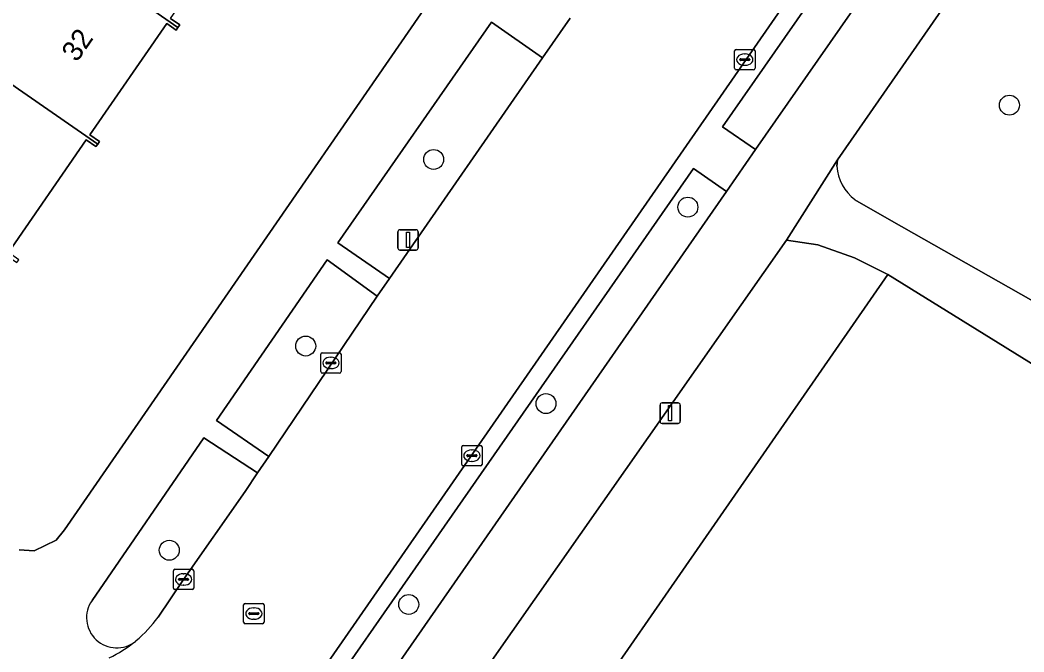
# Model space of a CAD drawing. Extents: x 160157 to 160921, y 381516 to 382045.
# Drawn here: x 160661.83 to 160711.12, y 381635.3 to 381666.31 of the extents above; entities that cross this region are included whole.
import ezdxf

# ---------------------------------------------------------------- set-up
doc = ezdxf.new("R2010")
doc.units = 0
for name, color, linetype in [('IMGEO_Berm_groen', 7, 'Continuous'), ('IMGEO_Boom', 7, 'Continuous'), ('IMGEO_Erf', 7, 'Continuous'), ('IMGEO_Fietspad_open', 7, 'Continuous'), ('IMGEO_Groenvoorziening', 7, 'Continuous'), ('IMGEO_Kolk', 7, 'Continuous'), ('IMGEO_Lichtmast', 7, 'Continuous'), ('IMGEO_Loofbos', 7, 'Continuous'), ('IMGEO_Pand', 7, 'Continuous'), ('IMGEO_Pand_nummerreeks', 7, 'Continuous'), ('IMGEO_Rijbaan_lokaal_open', 7, 'Continuous'), ('IMGEO_Rioolput', 7, 'Continuous'), ('IMGEO_Voetpad_gesloten', 7, 'Continuous'), ('IMGEO_Voetpad_open', 7, 'Continuous')]:
    doc.layers.add(name, color=color, linetype=linetype)

msp = doc.modelspace()

# ---------------------------------------------------------------- linework, layer by layer
at = {"layer": 'IMGEO_Berm_groen'}
for points in [[(160704.668, 381669.608), (160703.044, 381670.718), (160696.326, 381661.075), (160697.946, 381659.948)], [(160687.489, 381664.451), (160684.982, 381666.207), (160677.443, 381655.379), (160679.971, 381653.62)], [(160696.519, 381657.896), (160694.898, 381659.024), (160673.518, 381628.335), (160674.352, 381626.036)], [(160679.374, 381652.759), (160676.912, 381654.54), (160671.475, 381646.649), (160674.044, 381644.891)]]:
    msp.add_lwpolyline(points, close=True, dxfattribs=at)
for points in [[(160672.883, 381643.176), (160673.497, 381644.083), (160670.854, 381645.81), (160665.368, 381637.83)], [(160668.609, 381637.008), (160669.862, 381638.857), (160672.883, 381643.176)], [(160667.511, 381635.831), (160667.525, 381635.842), (160667.539, 381635.854)]]:
    msp.add_lwpolyline(points, dxfattribs=at)
for centre, radius, start, end in [((160666.58, 381636.981), 1.48, 145.0056, 308.9767), ((160663.575, 381640.603), 6.186, 309.8552, 324.4709)]:
    msp.add_arc(centre, radius, start, end, dxfattribs=at)
at = {"layer": 'IMGEO_Boom'}
for centre in [(160710.41, 381662.131), (160682.141, 381659.468), (160694.623, 381657.127), (160675.859, 381650.311), (160687.656, 381647.487), (160669.159, 381640.29), (160680.917, 381637.631)]:
    msp.add_circle(centre, 0.489, dxfattribs=at)
at = {"layer": 'IMGEO_Erf'}
for points in [[(160661.788, 381640.317), (160662.531, 381640.256), (160663.603, 381640.788), (160664.019, 381641.292), (160689.395, 381678.051)], [(160669.217, 381666.391), (160669.674, 381666.076), (160669.585, 381665.947), (160669.496, 381665.819), (160669.033, 381666.139), (160665.261, 381660.677), (160665.734, 381660.35), (160665.647, 381660.223), (160665.559, 381660.096), (160665.076, 381660.429), (160661.259, 381654.902)]]:
    msp.add_lwpolyline(points, dxfattribs=at)
at = {"layer": 'IMGEO_Fietspad_open'}
msp.add_lwpolyline([(160704.668, 381669.608), (160697.946, 381659.948), (160696.519, 381657.896), (160674.352, 381626.036), (160672.896, 381623.946), (160675.87, 381621.852), (160699.473, 381655.503), (160701.965, 381659.446), (160707.599, 381667.561)], dxfattribs=at)
at = {"layer": 'IMGEO_Groenvoorziening'}
for points in [[(160761.696, 381722.771), (160752.602, 381728.769), (160752.505, 381728.833), (160750.884, 381729.902), (160715.353, 381678.728), (160707.599, 381667.561), (160701.965, 381659.446), (160701.931, 381659.132)], [(160702.815, 381657.494), (160704.618, 381656.458), (160713.536, 381651.406), (160719.079, 381659.62), (160726.687, 381670.894), (160761.696, 381722.771)]]:
    msp.add_lwpolyline(points, dxfattribs=at)
msp.add_lwpolyline([(160704.448, 381653.821), (160702.806, 381654.642), (160701.006, 381655.279), (160699.473, 381655.503), (160675.87, 381621.852), (160677.664, 381620.541), (160679.219, 381619.682), (160680.2, 381618.885)], close=True, dxfattribs=at)
msp.add_arc((160704.233, 381659.317), 2.309, 184.5885, 232.1214, dxfattribs=at)
at = {"layer": 'IMGEO_Kolk'}
for p, q in [((160696.918, 381663.94), (160696.918, 381664.792)), ((160696.993, 381664.866), (160697.845, 381664.866)), ((160697.406, 381664.646), (160697.431, 381664.646)), ((160697.919, 381664.792), (160697.919, 381663.94)), ((160697.177, 381664.36), (160697.177, 381664.372)), ((160697.615, 381664.323), (160697.217, 381664.323)), ((160697.22, 381664.409), (160697.618, 381664.409)), ((160697.429, 381664.086), (160697.404, 381664.086)), ((160697.661, 381664.372), (160697.661, 381664.36)), ((160697.845, 381663.866), (160696.993, 381663.866)), ((160676.596, 381649.056), (160676.596, 381649.908)), ((160676.671, 381649.982), (160677.523, 381649.982)), ((160677.597, 381649.908), (160677.597, 381649.056)), ((160676.855, 381649.476), (160676.855, 381649.488)), ((160677.293, 381649.439), (160676.895, 381649.439)), ((160676.898, 381649.525), (160677.296, 381649.525)), ((160677.084, 381649.762), (160677.109, 381649.762)), ((160677.339, 381649.488), (160677.339, 381649.476)), ((160677.523, 381648.982), (160676.671, 381648.982)), ((160677.107, 381649.202), (160677.082, 381649.202)), ((160683.517, 381644.506), (160683.517, 381645.358)), ((160683.592, 381645.432), (160684.444, 381645.432)), ((160684.518, 381645.358), (160684.518, 381644.506)), ((160683.776, 381644.926), (160683.776, 381644.938)), ((160684.214, 381644.889), (160683.816, 381644.889)), ((160683.819, 381644.975), (160684.217, 381644.975)), ((160684.005, 381645.212), (160684.03, 381645.212)), ((160684.26, 381644.938), (160684.26, 381644.926)), ((160684.444, 381644.432), (160683.592, 381644.432)), ((160684.028, 381644.652), (160684.003, 381644.652)), ((160669.361, 381638.431), (160669.361, 381639.283)), ((160669.436, 381639.357), (160670.288, 381639.357)), ((160669.849, 381639.137), (160669.874, 381639.137)), ((160670.362, 381639.283), (160670.362, 381638.431)), ((160669.62, 381638.851), (160669.62, 381638.863)), ((160670.058, 381638.814), (160669.66, 381638.814)), ((160669.663, 381638.9), (160670.061, 381638.9)), ((160669.872, 381638.577), (160669.847, 381638.577)), ((160670.104, 381638.863), (160670.104, 381638.851)), ((160670.288, 381638.357), (160669.436, 381638.357))]:
    msp.add_line(p, q, dxfattribs=at)
for points in [[(160696.918, 381663.94), (160696.918, 381664.792)], [(160696.993, 381664.866), (160697.845, 381664.866)], [(160697.919, 381664.792), (160697.919, 381663.94)], [(160697.845, 381663.866), (160696.993, 381663.866)], [(160676.596, 381649.056), (160676.596, 381649.908)], [(160676.671, 381649.982), (160677.523, 381649.982)], [(160677.597, 381649.908), (160677.597, 381649.056)], [(160677.523, 381648.982), (160676.671, 381648.982)], [(160683.517, 381644.506), (160683.517, 381645.358)], [(160683.592, 381645.432), (160684.444, 381645.432)], [(160684.518, 381645.358), (160684.518, 381644.506)], [(160684.444, 381644.432), (160683.592, 381644.432)], [(160669.361, 381638.431), (160669.361, 381639.283)], [(160669.436, 381639.357), (160670.288, 381639.357)], [(160670.362, 381639.283), (160670.362, 381638.431)], [(160670.288, 381638.357), (160669.436, 381638.357)]]:
    msp.add_lwpolyline(points, dxfattribs=at)
for centre, radius, start, end in [((160696.995, 381664.79), 0.0765, 91.552, 178.448), ((160696.995, 381664.79), 0.0765, 91.552, 178.448), ((160697.843, 381664.79), 0.0765, 1.552, 88.448), ((160697.843, 381664.79), 0.0765, 1.552, 88.448), ((160697.217, 381664.369), 0.0403, 85.8775, 175.7526), ((160697.214, 381664.359), 0.0366, 178.938, 274.7102), ((160697.618, 381664.366), 0.043, 264.8664, 352.4533), ((160697.622, 381664.371), 0.0386, 1.7309, 96.639), ((160696.995, 381663.942), 0.0765, 181.552, 268.448), ((160696.995, 381663.942), 0.0765, 181.552, 268.448), ((160697.843, 381663.942), 0.0765, 271.552, 358.448), ((160697.843, 381663.942), 0.0765, 271.552, 358.448), ((160676.673, 381649.906), 0.0765, 91.552, 178.448), ((160676.673, 381649.906), 0.0765, 91.552, 178.448), ((160677.521, 381649.906), 0.0765, 1.552, 88.448), ((160677.521, 381649.906), 0.0765, 1.552, 88.448), ((160676.895, 381649.485), 0.0403, 85.8775, 175.7526), ((160676.892, 381649.475), 0.0366, 178.938, 274.7102), ((160677.296, 381649.482), 0.043, 264.8664, 352.4533), ((160677.3, 381649.487), 0.0386, 1.7309, 96.639), ((160676.673, 381649.058), 0.0765, 181.552, 268.448), ((160676.673, 381649.058), 0.0765, 181.552, 268.448), ((160677.521, 381649.058), 0.0765, 271.552, 358.448), ((160677.521, 381649.058), 0.0765, 271.552, 358.448), ((160683.594, 381645.356), 0.0765, 91.552, 178.448), ((160683.594, 381645.356), 0.0765, 91.552, 178.448), ((160684.442, 381645.356), 0.0765, 1.552, 88.448), ((160684.442, 381645.356), 0.0765, 1.552, 88.448), ((160683.816, 381644.935), 0.0403, 85.8775, 175.7526), ((160683.813, 381644.925), 0.0366, 178.938, 274.7102), ((160684.217, 381644.932), 0.043, 264.8664, 352.4533), ((160684.221, 381644.937), 0.0386, 1.7309, 96.639), ((160683.594, 381644.508), 0.0765, 181.552, 268.448), ((160683.594, 381644.508), 0.0765, 181.552, 268.448), ((160684.442, 381644.508), 0.0765, 271.552, 358.448), ((160684.442, 381644.508), 0.0765, 271.552, 358.448), ((160669.438, 381639.281), 0.0765, 91.552, 178.448), ((160669.438, 381639.281), 0.0765, 91.552, 178.448), ((160670.286, 381639.281), 0.0765, 1.552, 88.448), ((160670.286, 381639.281), 0.0765, 1.552, 88.448), ((160669.66, 381638.86), 0.0403, 85.8775, 175.7526), ((160669.657, 381638.85), 0.0366, 178.938, 274.7102), ((160670.061, 381638.857), 0.043, 264.8664, 352.4533), ((160670.065, 381638.862), 0.0386, 1.7309, 96.639), ((160669.438, 381638.433), 0.0765, 181.552, 268.448), ((160669.438, 381638.433), 0.0765, 181.552, 268.448), ((160670.286, 381638.433), 0.0765, 271.552, 358.448), ((160670.286, 381638.433), 0.0765, 271.552, 358.448)]:
    msp.add_arc(centre, radius, start, end, dxfattribs=at)
for centre, major_axis, ratio, start_param, end_param in [((160697.405, 381664.366), (-0.387, 0.002), 0.722429, 4.712389, 7.853982), ((160697.43, 381664.366), (-0.39, 0.002), 0.717154, 1.570796, 4.712389), ((160677.083, 381649.482), (-0.387, 0.002), 0.722429, 4.712389, 7.853982), ((160677.108, 381649.482), (-0.39, 0.002), 0.717154, 1.570796, 4.712389), ((160684.004, 381644.932), (-0.387, 0.002), 0.722429, 4.712389, 7.853982), ((160684.029, 381644.932), (-0.39, 0.002), 0.717154, 1.570796, 4.712389), ((160669.848, 381638.857), (-0.387, 0.002), 0.722429, 4.712389, 7.853982), ((160669.873, 381638.857), (-0.39, 0.002), 0.717154, 1.570796, 4.712389)]:
    msp.add_ellipse(centre, major_axis=major_axis, ratio=ratio, start_param=start_param, end_param=end_param, dxfattribs=at)
at = {"layer": 'IMGEO_Lichtmast'}
for p, q in [((160680.387, 381655.119), (160680.387, 381655.919)), ((160680.387, 381655.919), (160680.387, 381655.119)), ((160680.487, 381656.019), (160681.277, 381656.019)), ((160681.277, 381656.019), (160680.487, 381656.019)), ((160681.377, 381655.919), (160681.377, 381655.119)), ((160681.377, 381655.119), (160681.377, 381655.919)), ((160681.277, 381655.019), (160680.487, 381655.019)), ((160680.487, 381655.019), (160681.277, 381655.019)), ((160693.255, 381646.617), (160693.255, 381647.417)), ((160693.255, 381647.417), (160693.255, 381646.617)), ((160693.355, 381647.517), (160694.145, 381647.517)), ((160694.145, 381647.517), (160693.355, 381647.517)), ((160694.245, 381647.417), (160694.245, 381646.617)), ((160694.245, 381646.617), (160694.245, 381647.417)), ((160694.145, 381646.517), (160693.355, 381646.517)), ((160693.355, 381646.517), (160694.145, 381646.517))]:
    msp.add_line(p, q, dxfattribs=at)
for points in [[(160680.807, 381655.894), (160680.957, 381655.894), (160680.957, 381655.144), (160680.807, 381655.144), (160680.807, 381655.894)], [(160693.675, 381647.392), (160693.825, 381647.392), (160693.825, 381646.642), (160693.675, 381646.642), (160693.675, 381647.392)]]:
    msp.add_lwpolyline(points, dxfattribs=at)
for centre, start, end in [((160680.487, 381655.919), 90, 180), ((160680.487, 381655.919), 90, 180), ((160681.277, 381655.919), 0, 90), ((160681.277, 381655.919), 360, 90), ((160680.487, 381655.119), 180, 270), ((160680.487, 381655.119), 180, 270), ((160681.277, 381655.119), 270, 0), ((160681.277, 381655.119), 270, 0), ((160693.355, 381647.417), 90, 180), ((160693.355, 381647.417), 90, 180), ((160694.145, 381647.417), 0, 90), ((160694.145, 381647.417), 360, 90), ((160693.355, 381646.617), 180, 270), ((160693.355, 381646.617), 180, 270), ((160694.145, 381646.617), 270, 0), ((160694.145, 381646.617), 270, 0)]:
    msp.add_arc(centre, 0.1, start, end, dxfattribs=at)
at = {"layer": 'IMGEO_Loofbos'}
msp.add_lwpolyline([(160718.033, 381645.133), (160716.09, 381646.604), (160704.448, 381653.821), (160680.2, 381618.885), (160723.425, 381583.938), (160730.737, 381577.745), (160731.834, 381578.912), (160706.24, 381600.002), (160694.373, 381609.558), (160697.176, 381613.023), (160713, 381600.315), (160734.93, 381582.203), (160738.537, 381585.616), (160753.817, 381601.153), (160754.288, 381601.948)], dxfattribs=at)
at = {"layer": 'IMGEO_Pand'}
for points in [[(160666.67, 381676.54), (160665.663, 381677.235), (160663.965, 381674.776), (160664.973, 381674.081), (160662.677, 381670.756), (160669.585, 381665.947), (160669.674, 381666.076), (160669.217, 381666.391), (160673.012, 381671.887), (160673.413, 381671.61), (160673.499, 381671.735)], [(160658.696, 381665.021), (160665.647, 381660.223), (160665.734, 381660.35), (160665.261, 381660.677), (160669.033, 381666.139), (160669.496, 381665.819), (160669.585, 381665.947), (160662.677, 381670.756), (160661.653, 381671.463), (160659.963, 381669.017), (160660.974, 381668.32)], [(160658.696, 381665.021), (160657.624, 381665.725), (160655.956, 381663.31), (160657.043, 381662.559), (160654.728, 381659.207), (160661.671, 381654.406), (160661.77, 381654.549), (160661.259, 381654.902), (160665.076, 381660.429), (160665.559, 381660.096), (160665.647, 381660.223)]]:
    msp.add_lwpolyline(points, close=True, dxfattribs=at)
at = {"layer": 'IMGEO_Rijbaan_lokaal_open'}
for points in [[(160669.597, 381624.241), (160673.052, 381629.169), (160742.168, 381728.75), (160744.459, 381732.031), (160749.187, 381738.841), (160756.939, 381750), (160765.763, 381763.144), (160772.954, 381773.374), (160774.36, 381775.443), (160780.995, 381784.58)], [(160688.846, 381666.406), (160687.489, 381664.451), (160679.971, 381653.62), (160679.374, 381652.759), (160674.044, 381644.891), (160673.497, 381644.083), (160672.883, 381643.176), (160669.862, 381638.857), (160668.609, 381637.008)], [(160667.539, 381635.854), (160667.525, 381635.842), (160667.511, 381635.831)]]:
    msp.add_lwpolyline(points, dxfattribs=at)
for centre, radius, start, end in [((160663.575, 381640.603), 6.186, 309.8552, 324.4709), ((160663.579, 381640.601), 6.182, 295.212, 309.5018)]:
    msp.add_arc(centre, radius, start, end, dxfattribs=at)
at = {"layer": 'IMGEO_Rioolput'}
for p, q in [((160672.811, 381636.757), (160672.811, 381637.609)), ((160672.886, 381637.683), (160673.738, 381637.683)), ((160673.299, 381637.463), (160673.324, 381637.463)), ((160673.812, 381637.609), (160673.812, 381636.757)), ((160673.07, 381637.177), (160673.07, 381637.189)), ((160673.508, 381637.14), (160673.11, 381637.14)), ((160673.113, 381637.226), (160673.511, 381637.226)), ((160673.554, 381637.189), (160673.554, 381637.177)), ((160673.738, 381636.683), (160672.886, 381636.683)), ((160673.322, 381636.903), (160673.297, 381636.903))]:
    msp.add_line(p, q, dxfattribs=at)
for points in [[(160672.811, 381636.757), (160672.811, 381637.609)], [(160672.886, 381637.683), (160673.738, 381637.683)], [(160673.812, 381637.609), (160673.812, 381636.757)], [(160673.738, 381636.683), (160672.886, 381636.683)]]:
    msp.add_lwpolyline(points, dxfattribs=at)
for centre, radius, start, end in [((160672.888, 381637.607), 0.0765, 91.552, 178.448), ((160672.888, 381637.607), 0.0765, 91.552, 178.448), ((160673.736, 381637.607), 0.0765, 1.552, 88.448), ((160673.736, 381637.607), 0.0765, 1.552, 88.448), ((160673.11, 381637.186), 0.0403, 85.8775, 175.7526), ((160673.107, 381637.176), 0.0366, 178.938, 274.7102), ((160673.511, 381637.183), 0.043, 264.8664, 352.4533), ((160673.515, 381637.188), 0.0386, 1.7309, 96.639), ((160672.888, 381636.759), 0.0765, 181.552, 268.448), ((160672.888, 381636.759), 0.0765, 181.552, 268.448), ((160673.736, 381636.759), 0.0765, 271.552, 358.448), ((160673.736, 381636.759), 0.0765, 271.552, 358.448)]:
    msp.add_arc(centre, radius, start, end, dxfattribs=at)
for centre, major_axis, ratio, start_param, end_param in [((160673.298, 381637.183), (-0.387, 0.002), 0.722429, 4.712389, 7.853982), ((160673.323, 381637.183), (-0.39, 0.002), 0.717154, 1.570796, 4.712389)]:
    msp.add_ellipse(centre, major_axis=major_axis, ratio=ratio, start_param=start_param, end_param=end_param, dxfattribs=at)
at = {"layer": 'IMGEO_Voetpad_gesloten'}
for points in [[(160701.931, 381659.132), (160701.965, 381659.446), (160699.473, 381655.503), (160701.006, 381655.279), (160702.806, 381654.642), (160704.448, 381653.821), (160716.09, 381646.604), (160718.033, 381645.133), (160747.945, 381612.756), (160753.498, 381605.754), (160754.118, 381604.777)], [(160719.708, 381647.47), (160717.841, 381648.827), (160713.536, 381651.406), (160704.618, 381656.458), (160702.815, 381657.494)]]:
    msp.add_lwpolyline(points, dxfattribs=at)
msp.add_arc((160704.233, 381659.317), 2.309, 184.5885, 232.1214, dxfattribs=at)
at = {"layer": 'IMGEO_Voetpad_open'}
for points in [[(160742.168, 381728.75), (160673.052, 381629.169), (160673.518, 381628.335), (160694.898, 381659.024), (160696.519, 381657.896), (160697.946, 381659.948), (160696.326, 381661.075), (160703.044, 381670.718)], [(160689.395, 381678.051), (160664.019, 381641.292), (160663.603, 381640.788), (160662.531, 381640.256), (160661.788, 381640.317)], [(160670.854, 381645.81), (160673.497, 381644.083), (160674.044, 381644.891), (160671.475, 381646.649), (160676.912, 381654.54), (160679.374, 381652.759), (160679.971, 381653.62), (160677.443, 381655.379), (160684.982, 381666.207), (160687.489, 381664.451), (160688.846, 381666.406)], [(160665.368, 381637.83), (160670.854, 381645.81)]]:
    msp.add_lwpolyline(points, dxfattribs=at)
for centre, radius, start, end in [((160666.58, 381636.981), 1.48, 145.0056, 308.9767), ((160663.579, 381640.601), 6.182, 295.212, 309.5018)]:
    msp.add_arc(centre, radius, start, end, dxfattribs=at)

# ---------------------------------------------------------------- texts
at = {"layer": 'IMGEO_Pand_nummerreeks'}
msp.add_text('32', height=1, rotation=55.3563, dxfattribs=at).set_placement((160664.623, 381664.201))

doc.saveas('drawing.dxf')
